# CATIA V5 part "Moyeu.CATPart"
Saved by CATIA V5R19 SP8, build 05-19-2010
Part number: Moyeu
Bounding box of the stored display mesh (mm): x -62 to -19, y -10.5 to 10.5, z -9.5 to 13
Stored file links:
  G:\EU_thinkMotion\CFAO_2010\MMS_groupe3\MMS_groupe3\jbonnamy\jbonnamy_cfao\Moyeu.CATPart
  G:\EU_thinkMotion\CFAO_2010\MMS_groupe3\MMS_groupe3\jbonnamy\jbonnamy_cfao\jbonnamy_suspension.arriere.directionnelle.CATProduct
  G:\EU_thinkMotion\CFAO_2010\MMS_groupe3\MMS_groupe3\jbonnamy\jbonnamy_cfao\SKL.general.CATPart
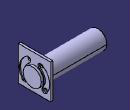
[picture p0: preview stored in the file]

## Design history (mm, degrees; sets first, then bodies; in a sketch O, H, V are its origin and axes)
External parameters (linked from other documents)
  External.Epaisseur.support.10 = 1.5 mm
  External.Largeur.porte.moyeu = 21 mm
  External.Hauteur.porte.moyeu = 22.5 mm
  External.Distance.fixation.24.centre.pignon = 9.5 mm
  External.Diametre.moyeu = 12 mm
  External.Diametre.vis.fixation = 2 mm
  External.Longueur.moyeu = 40 mm
Set1
  Plane1 "Plan.moyeu": linked copy from another document
  Point1 "Centre.pignon": linked copy from another document
Body1 (main body)
  Sketch1 on Plane1, origin (-20.5, 0, 0), H (0, 1, 0), V (0, 0, 1)
    line L1 (10.5, 13) -> (-10.5, 13)
    line L2 (-10.5, 13) -> (-10.5, -9.5)
    line L3 (-10.5, -9.5) -> (10.5, -9.5)
    line L4 (10.5, -9.5) -> (10.5, 13)
    distance L1 L3 = 22.5 {= External.Hauteur.porte.moyeu}
    distance L2 L4 = 21 {= External.Largeur.porte.moyeu}
    distance L4 V = 10.5 {= External.Largeur.porte.moyeu /2}
    distance L3 H = 9.5 {= External.Distance.fixation.24.centre.pignon}
  Pad1: profile Sketch1, direction (-1, 0, 0), length 1.5 {= External.Epaisseur.support.10}
  Sketch2 on Plane1, origin (-20.5, 0, 0), H (0, 1, 0), V (0, 0, 1)
    construction arc A1 centre (0, 0) radius 8.25 from (-4, 7.2154) to (-6.5622, -5) ccw
    point P1 (-4, 7.2154)
    point P2 (-6.5622, -5)
    arc A2 centre (-4, 7.2154) radius 1.75 from (-4.8485, 8.746) to (-3.1515, 5.6849) cw
    arc A3 centre (-6.5622, -5) radius 1.75 from (-5.1702, -3.9394) to (-7.9542, -6.0606) cw
    arc A4 centre (0, 0) radius 6.5 from (-3.1515, 5.6849) to (-5.1702, -3.9394) ccw
    arc A5 centre (0, 0) radius 10 from (-7.9542, -6.0606) to (-4.8485, 8.746) cw
    construction arc A6 centre (0, 0) radius 8.25 from (6.5622, -5) to (4, 7.2154) ccw
    arc A7 centre (6.5622, -5) radius 1.75 from (7.9542, -6.0606) to (5.1702, -3.9394) cw
    arc A8 centre (4, 7.2154) radius 1.75 from (3.1515, 5.6849) to (4.8485, 8.746) cw
    arc A9 centre (0, 0) radius 6.5 from (5.1702, -3.9394) to (3.1515, 5.6849) ccw
    arc A10 centre (0, 0) radius 10 from (4.8485, 8.746) to (7.9542, -6.0606) cw
    distance P1 V = 4
    distance P2 H = 5
    radius A1 = 8.25
    radius A3 = 1.75
    radius A6 = 8.25
    radius A8 = 1.75
  Pocket1: profile Sketch2, direction (-1, 0, 0), length 0.75 {= External.Epaisseur.support.10 /2}
  Sketch3 on end face of Pad1, origin (-22, 0, 0), H (0, 1, 0), V (0, 0, 1)
    circle A1 centre (0, 0) radius 6
    point P1 (0, 0)
    reference projected point E1 (0, 0) from Point1
    radius A1 = 6 {= External.Diametre.moyeu /2}
    distance P1 E1 = 0
  Pad2: profile Sketch3, direction (-1, 0, 0), length 40 {= External.Longueur.moyeu}, opposite side length 3 {= 2*External.Epaisseur.support.10}
  Sketch4 on end face of Pad1, origin (-22, 0, 0), H (0, 1, 0), V (0, 0, 1)
    circle A1 centre (-4, 7.2154) radius 1
    point P1 (-4, 7.2154)
    circle A2 centre (4, 7.2154) radius 1
    point P2 (4, 7.2154)
    circle A3 centre (6.5622, -5) radius 1
    point P3 (6.5622, -5)
    circle A4 centre (-6.5622, -5) radius 1
    point P4 (-6.5622, -5)
    reference projected point E1 (0, 0) from Point1
    reference projected point E2 (0, 0) from Point1
    reference projected point E3 (0, 0) from Point1
    reference projected point E4 (0, 0) from Point1
    radius A4 = 1 {= External.Diametre.vis.fixation /2}
    radius A1 = 1 {= External.Diametre.vis.fixation /2}
    radius A2 = 1 {= External.Diametre.vis.fixation /2}
    radius A3 = 1 {= External.Diametre.vis.fixation /2}
    distance P4 E1 = 8.25
    distance P1 E2 = 8.25
    distance P2 E3 = 8.25
    distance P3 E4 = 8.25
    distance P2 V = 4
    distance P1 V = 4
    distance P4 H = 5
    distance P3 H = 5
  Pocket2: profile Sketch4, direction (1, 0, 0), length 1.5 {= External.Epaisseur.support.10}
